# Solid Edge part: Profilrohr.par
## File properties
Username: bmolnar
Dokumentum tartalom típus: 0
Author: bmolnar
Last saved by: bmolnar
Revision: 79
Sűrűség: 0,000 kg/m^3
Pontosság: 0,990
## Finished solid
Body 1: solid body, 91 faces, 266 edges, 176 vertices.
  Faces by surface: plane 46, cylinder 45
  Edges by curve: line 176, circle 90
Bounding box of the edges (mm): 49.000 x 49.000 x 35.800, from (-24.5, -24.5, 0) to (24.5, 24.5, 35.8).
Cylindrical faces by radius (mm): R0.15 x20, R0.25 x20, R8 x4, R16 x1
Planar faces by outward normal: +x 11, +y 11, +z 1, -x 11, -y 11, -z 1
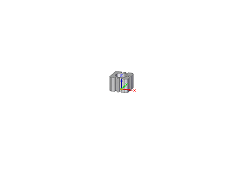
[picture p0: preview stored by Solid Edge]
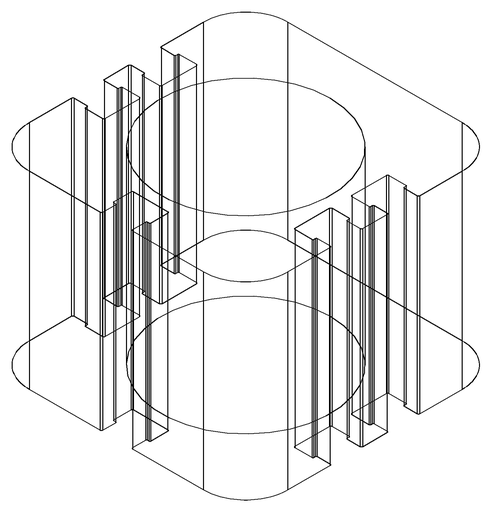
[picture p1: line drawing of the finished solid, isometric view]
